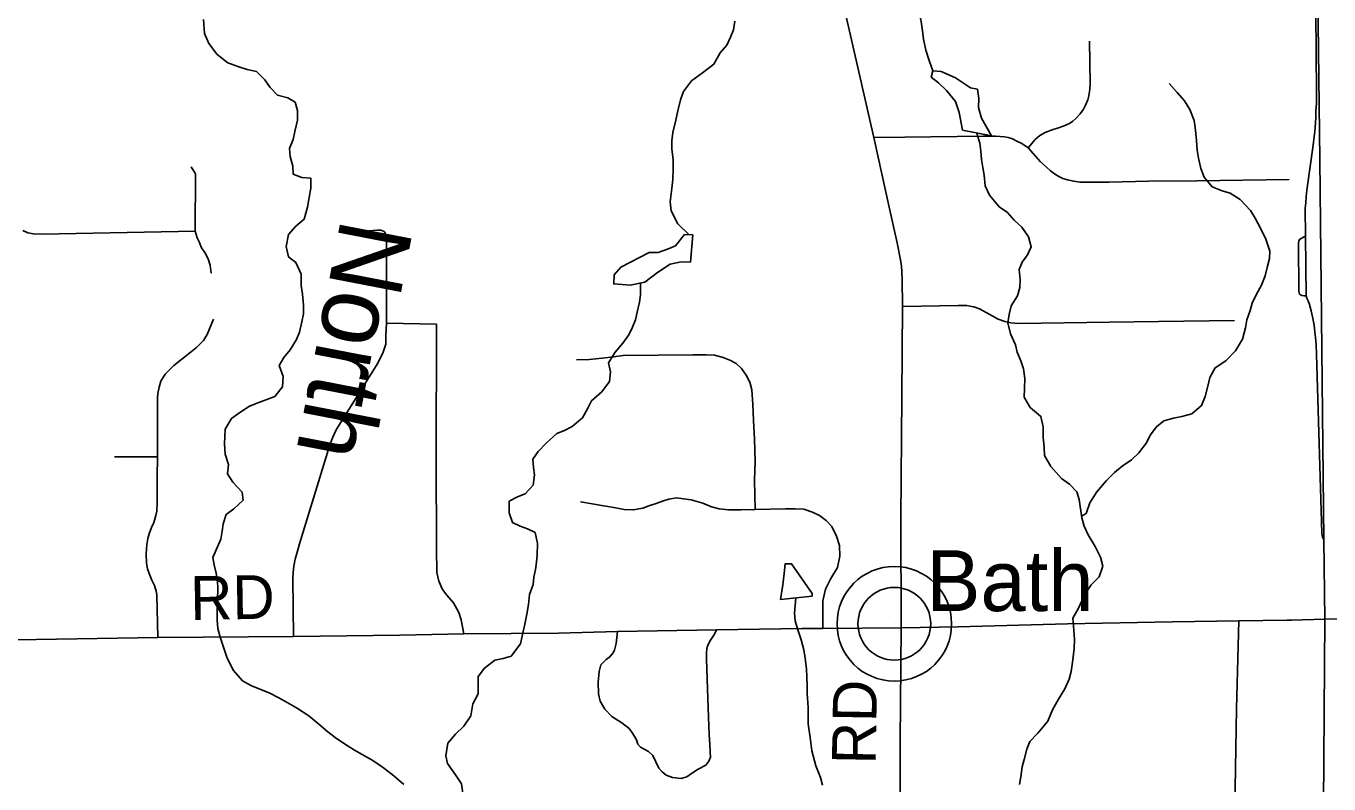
# Model space of a CAD drawing. Extents: x 0 to 34, y 0 to 22.
# Drawn here: x 4.739 to 6.431, y 14.753 to 15.737 of the extents above; entities that cross this region are included whole.
import ezdxf

# ---------------------------------------------------------------- set-up
doc = ezdxf.new("R2010")
doc.units = 0
for name, color, linetype in [('GM_X_County_Road', 7, 'Continuous'), ('GM_X_County_Road_Text', 7, 'Continuous'), ('GM_X_Interchange_Ramps', 7, 'Continuous'), ('GM_X_Interstate_Route', 7, 'Continuous'), ('GM_X_Minor_Lake', 7, 'Continuous'), ('GM_X_Minor_River', 7, 'Continuous'), ('GM_X_Minor_River_Text', 7, 'Continuous'), ('GM_X_Township_Road', 7, 'Continuous'), ('GM_X_Unincorporated', 7, 'Continuous'), ('GM_X_Unincorporated_Location', 7, 'Continuous'), ('GM_X_Unincorporated_Text', 7, 'Continuous')]:
    doc.layers.add(name, color=color, linetype=linetype)

msp = doc.modelspace()

# ---------------------------------------------------------------- linework, layer by layer
at = {"layer": 'GM_X_County_Road'}
for points in [[(5.8717, 14.1), (5.8713, 14.2404), (5.872, 14.4243), (5.8732, 14.6187), (5.8739, 14.809), (5.875, 14.9557), (5.8744, 15.0978), (5.8759, 15.2554), (5.8769, 15.3727), (5.8762, 15.4088), (5.8752, 15.4255), (5.8739, 15.4356), (5.87, 15.4555), (5.8595, 15.5018), (5.8396, 15.592), (5.8151, 15.698), (5.7885, 15.8153), (5.784, 15.8367), (5.7797, 15.8558), (5.777, 15.8765)], [(5.875, 14.9557), (5.9488, 14.9569), (6.091, 14.9609), (6.2275, 14.9636), (6.3137, 14.9647), (6.3762, 14.9657), (6.3821, 14.9658)], [(6.3821, 14.9658), (6.425, 14.9668), (6.4444, 14.9673), (6.542, 14.9681), (6.5587, 14.9685)], [(4.3412, 14.9346), (4.511, 14.937), (4.6987, 14.9398), (4.9098, 14.943), (5.086, 14.9444), (5.2239, 14.9463), (5.3069, 14.9479), (5.4298, 14.9489), (5.5067, 14.9509), (5.635, 14.953), (5.7464, 14.9549), (5.7732, 14.955), (5.875, 14.9557)]]:
    msp.add_lwpolyline(points, dxfattribs=at)
at = {"layer": 'GM_X_Interchange_Ramps'}
for points in [[(6.4131, 15.7649), (6.4139, 15.716), (6.4143, 15.6364), (6.4137, 15.6266), (6.4133, 15.6177), (6.4129, 15.6116), (6.4125, 15.605), (6.412, 15.5999), (6.4115, 15.5936), (6.41, 15.5821), (6.4019, 15.5238), (6.4008, 15.5151), (6.4003, 15.5074), (6.3998, 15.5003), (6.4001, 15.4641), (6.4009, 15.3867), (6.4018, 15.3837), (6.4036, 15.38), (6.4051, 15.3752), (6.4074, 15.3671), (6.4091, 15.3595), (6.4112, 15.3483), (6.4124, 15.3393), (6.4132, 15.3325), (6.414, 15.3232), (6.4144, 15.3109), (6.4148, 15.2962), (6.4213, 15.0791), (6.4216, 15.0755), (6.4224, 15.0727), (6.4239, 15.0701)], [(6.4001, 15.4641), (6.3976, 15.4629), (6.3953, 15.4615), (6.3928, 15.46), (6.3913, 15.4579), (6.3909, 15.4552), (6.3913, 15.392), (6.3924, 15.3889), (6.3953, 15.3872), (6.3983, 15.3866), (6.4009, 15.3867)]]:
    msp.add_lwpolyline(points, dxfattribs=at)
at = {"layer": 'GM_X_Interstate_Route'}
msp.add_lwpolyline([(6.419, 14.1), (6.4211, 14.4229), (6.425, 14.9668), (6.4239, 15.0701), (6.4187, 15.5636), (6.4161, 15.7761), (6.4147, 15.8905), (6.4116, 16.1673), (6.4105, 16.2537), (6.4089, 16.369), (6.4076, 16.42), (6.4063, 16.4687), (6.4018, 16.5458), (6.3968, 16.6242), (6.3897, 16.7077), (6.3766, 16.863), (6.3715, 16.9335)], dxfattribs=at)
at = {"layer": 'GM_X_Minor_Lake'}
for points in [[(5.9925, 15.5942), (5.9794, 15.6173), (5.9754, 15.6309), (5.9757, 15.6427), (5.9741, 15.6548), (5.965, 15.6566), (5.9455, 15.6694), (5.9268, 15.6779), (5.9162, 15.6786), (5.914, 15.6706), (5.9236, 15.6631), (5.9339, 15.6533), (5.9454, 15.639), (5.9505, 15.6246), (5.9545, 15.6018)], [(5.9545, 15.6018), (5.9925, 15.5942)], [(5.6043, 15.4656), (5.5937, 15.4663), (5.5817, 15.4513), (5.5714, 15.4471), (5.5593, 15.4428), (5.5476, 15.4427), (5.5109, 15.4237), (5.5023, 15.4137), (5.5017, 15.402), (5.5229, 15.4003), (5.5419, 15.4042), (5.5584, 15.4169), (5.575, 15.4277), (5.5894, 15.4305), (5.6016, 15.4302)], [(5.6016, 15.4302), (5.6043, 15.4656)], [(5.7596, 14.9968), (5.7592, 15.0002), (5.7326, 15.0387), (5.7243, 15.0386), (5.7229, 15.026), (5.7215, 15.0116), (5.7182, 14.9926)], [(5.7182, 14.9926), (5.7596, 14.9968)]]:
    msp.add_lwpolyline(points, dxfattribs=at)
at = {"layer": 'GM_X_Minor_River'}
for points in [[(5.9162, 15.6786), (5.9115, 15.6919), (5.9072, 15.7055), (5.9041, 15.7195), (5.9025, 15.7305), (5.9008, 15.7427), (5.898, 15.7567), (5.8915, 15.7769)], [(5.1889, 14.7836), (5.1748, 14.7911), (5.1649, 14.7967), (5.1519, 14.8049), (5.14, 14.8132), (5.1305, 14.8207), (5.1186, 14.8308), (5.1056, 14.8413), (5.0896, 14.8518), (5.0774, 14.8589), (5.0667, 14.8649), (5.0553, 14.8709), (5.0412, 14.8764), (5.0313, 14.8805), (5.0195, 14.8869), (5.0079, 14.9001), (4.9998, 14.9163), (4.9905, 14.9436), (4.9877, 14.955), (4.9869, 14.9656), (4.9867, 14.9789), (4.987, 14.9922), (4.9876, 15.0066), (4.9872, 15.0161), (4.9852, 15.0267), (4.9828, 15.0373), (4.9812, 15.0468), (4.9916, 15.0709), (4.993, 15.0811), (4.9945, 15.0906), (4.9985, 15.1028), (5.0083, 15.1101), (5.0204, 15.1213), (5.0191, 15.1319), (5.0072, 15.1447), (4.9999, 15.1556), (5.0013, 15.1678), (4.9971, 15.1811), (4.9962, 15.1944), (4.9965, 15.2039), (4.9971, 15.2137), (5.0054, 15.2275), (5.0163, 15.2352), (5.0287, 15.2433), (5.0408, 15.2483), (5.0514, 15.2522), (5.0616, 15.2561), (5.0714, 15.2684), (5.0724, 15.2817), (5.0674, 15.2961), (5.0733, 15.3064), (5.0816, 15.3163), (5.0898, 15.3301), (5.0935, 15.3396), (5.0968, 15.353), (5.0986, 15.3632), (5.0989, 15.3746), (5.0976, 15.3887), (5.0956, 15.4001), (5.0959, 15.4145), (5.0889, 15.43), (5.0794, 15.4371), (5.0762, 15.4508), (5.0795, 15.4664), (5.0889, 15.4771), (5.0998, 15.4863), (5.1042, 15.5016), (5.106, 15.5141), (5.1085, 15.5263), (5.1084, 15.5392), (5.0966, 15.5402), (5.0856, 15.5447), (5.0851, 15.555), (5.0816, 15.5675), (5.0807, 15.5777), (5.0856, 15.5895), (5.0874, 15.5998), (5.091, 15.6147), (5.0909, 15.6272), (5.0882, 15.6378), (5.0783, 15.6434), (5.0649, 15.6471), (5.0557, 15.6569), (5.0484, 15.6671), (5.0377, 15.6776), (5.0256, 15.6805), (5.0149, 15.6838), (5.0004, 15.689), (4.9867, 15.6999), (4.9759, 15.7139), (4.9701, 15.7271), (4.9688, 15.7453)], [(5.5995, 15.4659), (5.5848, 15.4799), (5.5763, 15.4969), (5.5751, 15.5086), (5.5772, 15.5258), (5.5786, 15.5375), (5.5789, 15.5516), (5.5787, 15.563), (5.5771, 15.5774), (5.577, 15.5877), (5.5784, 15.5987), (5.5825, 15.6147), (5.5854, 15.6288), (5.5887, 15.6421), (5.5924, 15.6516), (5.6029, 15.6658), (5.6168, 15.6762), (5.6315, 15.6873), (5.6401, 15.7019), (5.6484, 15.7118), (5.6532, 15.7225), (5.6573, 15.732), (5.6591, 15.7431)], [(6.1093, 15.1007), (6.1153, 15.1042), (6.1201, 15.1179), (6.1291, 15.1324), (6.1415, 15.147), (6.152, 15.1573), (6.1618, 15.1654), (6.1739, 15.1739), (6.1837, 15.1827), (6.1938, 15.1957), (6.1983, 15.2056), (6.2065, 15.2167), (6.2163, 15.2244), (6.2288, 15.2279), (6.2394, 15.2299), (6.2523, 15.2335), (6.2651, 15.2442), (6.2699, 15.2561), (6.2732, 15.2694), (6.2757, 15.2804), (6.2828, 15.293), (6.2968, 15.3023), (6.3092, 15.3153), (6.3182, 15.3302), (6.3222, 15.3451), (6.324, 15.3553), (6.3281, 15.3675), (6.331, 15.377), (6.3359, 15.3877), (6.343, 15.4003), (6.3478, 15.4125), (6.3504, 15.4232), (6.3533, 15.435), (6.3536, 15.4445), (6.3485, 15.46), (6.3415, 15.4744), (6.3346, 15.4873), (6.3288, 15.4975), (6.3154, 15.5118), (6.3024, 15.52), (6.2918, 15.5229), (6.2788, 15.5281), (6.2685, 15.5406), (6.2642, 15.5519), (6.261, 15.5652), (6.2594, 15.5758), (6.2585, 15.588), (6.2573, 15.6016), (6.2557, 15.6142), (6.2498, 15.6285), (6.2429, 15.6395), (6.2333, 15.6504), (6.223, 15.6621)], [(6.0234, 15.3229), (6.0168, 15.3373), (6.0133, 15.3517), (6.0151, 15.3623), (6.018, 15.3734), (6.0262, 15.3867), (6.0292, 15.3974), (6.0295, 15.4077), (6.0282, 15.4206), (6.0323, 15.4301), (6.039, 15.44), (6.0439, 15.4503), (6.0403, 15.4632), (6.0315, 15.4757), (6.0219, 15.4847), (6.0127, 15.4953), (6.0028, 15.5016), (5.9898, 15.5171), (5.984, 15.5292), (5.9827, 15.5432), (5.9811, 15.5531), (5.9791, 15.5637), (5.9786, 15.5743), (5.977, 15.5846), (5.9731, 15.5975)], [(5.3058, 14.741), (5.3038, 14.7532), (5.2961, 14.7649), (5.2857, 14.7796), (5.2837, 14.7894), (5.2862, 14.8058), (5.296, 14.8177), (5.3072, 14.828), (5.3162, 14.8414), (5.3188, 14.857), (5.3258, 14.87), (5.3257, 14.8806), (5.3256, 14.8924), (5.3339, 14.9035), (5.3471, 14.9139), (5.3581, 14.9159), (5.3683, 14.919), (5.3807, 14.9347), (5.3843, 14.9507), (5.3861, 14.9606), (5.389, 14.9732), (5.3912, 14.9861), (5.3922, 14.999), (5.397, 15.012), (5.3981, 15.0215), (5.3999, 15.0314), (5.4013, 15.0409), (5.4024, 15.0504), (5.4026, 15.0652), (5.3995, 15.0792), (5.3895, 15.0841), (5.38, 15.0878), (5.3701, 15.0926), (5.3658, 15.1048), (5.3661, 15.12), (5.3766, 15.1257), (5.3865, 15.1296), (5.397, 15.1408), (5.3988, 15.1544), (5.3976, 15.1639), (5.3967, 15.1746), (5.4034, 15.1845), (5.4143, 15.1956), (5.4279, 15.2079), (5.4377, 15.2118), (5.4479, 15.2172), (5.4611, 15.2283), (5.4682, 15.2406), (5.473, 15.2501), (5.4862, 15.262), (5.496, 15.2754), (5.4974, 15.2879), (5.495, 15.2997), (5.5036, 15.3135), (5.5134, 15.3253), (5.5212, 15.336), (5.5261, 15.346), (5.5298, 15.3555), (5.532, 15.3654), (5.5353, 15.3783), (5.5363, 15.3878), (5.5365, 15.4031)], [(6.0286, 14.7524), (6.0304, 14.7623), (6.0322, 14.7752), (6.0347, 14.7847), (6.038, 14.798), (6.0421, 14.8083), (6.0526, 14.8191), (6.0654, 14.8344), (6.0713, 14.8493), (6.0792, 14.863), (6.0874, 14.8764), (6.093, 14.889), (6.0959, 14.8992), (6.0981, 14.9141), (6.0998, 14.9289), (6.1001, 14.9399), (6.0992, 14.9528), (6.0979, 14.9684), (6.1047, 14.9802), (6.1099, 14.9917), (6.1147, 15.0012), (6.1218, 15.0115), (6.132, 15.0219), (6.1368, 15.0356), (6.134, 15.0474), (6.1271, 15.0614), (6.1178, 15.0765), (6.1128, 15.0878), (6.1097, 15.0984), (6.106, 15.1223), (6.1029, 15.1322), (6.0937, 15.1423), (6.0834, 15.1495), (6.0692, 15.1649), (6.0611, 15.1793), (6.0606, 15.1899), (6.0594, 15.2032), (6.0596, 15.2165), (6.0565, 15.2301), (6.0427, 15.2418), (6.0346, 15.255), (6.0353, 15.2664), (6.0355, 15.2793), (6.0339, 15.2918), (6.0304, 15.3021), (6.0258, 15.3134), (6.0234, 15.3229)], [(5.7728, 14.7515), (5.7704, 14.7613), (5.7642, 14.7765), (5.7591, 14.7962), (5.7567, 14.8133), (5.7542, 14.8311), (5.7541, 14.8524), (5.7531, 14.8706), (5.753, 14.8801), (5.7525, 14.8926), (5.7521, 14.9021), (5.7501, 14.9165), (5.7484, 14.9271), (5.7449, 14.94), (5.7406, 14.9529), (5.7375, 14.9646), (5.7366, 14.9749), (5.7383, 14.9946)], [(5.229, 14.7525), (5.216, 14.7634), (5.2026, 14.7739), (5.1889, 14.7836)]]:
    msp.add_lwpolyline(points, dxfattribs=at)
at = {"layer": 'GM_X_Township_Road'}
msp.add_line((4.8533, 15.1775), (4.9092, 15.1775), dxfattribs=at)
for points in [[(6.0398, 15.5787), (6.049, 15.5893), (6.0551, 15.5946), (6.062, 15.5986), (6.0711, 15.602), (6.0791, 15.6045), (6.0868, 15.6072), (6.0936, 15.6104), (6.098, 15.6135), (6.1017, 15.6168), (6.1074, 15.6226), (6.1118, 15.6288), (6.1145, 15.6342), (6.1172, 15.6411), (6.1187, 15.6462), (6.1201, 15.6548), (6.1204, 15.6622), (6.1196, 15.7172)], [(5.8396, 15.592), (5.8796, 15.5925), (5.9815, 15.5937), (5.9976, 15.5939), (6.0036, 15.5934), (6.009, 15.5929), (6.0141, 15.592), (6.0195, 15.5902), (6.0254, 15.5875), (6.0317, 15.5841), (6.0398, 15.5787), (6.0561, 15.5605), (6.0635, 15.5539), (6.0689, 15.5488), (6.074, 15.5451), (6.0799, 15.5416), (6.0851, 15.539), (6.0909, 15.5372), (6.0991, 15.5352), (6.1072, 15.5342), (6.145, 15.5343), (6.1962, 15.5355), (6.2588, 15.536), (6.3787, 15.5374)], [(4.9788, 15.4161), (4.9775, 15.4266), (4.975, 15.4347), (4.9706, 15.443), (4.9664, 15.449), (4.9635, 15.4565), (4.9607, 15.4619), (4.9582, 15.4706), (4.9584, 15.5448), (4.9531, 15.554)], [(4.7342, 15.4713), (4.7409, 15.4685), (4.748, 15.4669), (4.7593, 15.4667), (4.9582, 15.4706)], [(5.086, 14.9444), (5.0851, 15.0195), (5.0853, 15.0274), (5.0863, 15.0356), (5.0878, 15.0447), (5.0903, 15.0522), (5.0938, 15.0648), (5.1331, 15.1931), (5.1371, 15.2032), (5.139, 15.2078), (5.1411, 15.2127), (5.1945, 15.2978), (5.2019, 15.3121), (5.2056, 15.3239), (5.2058, 15.3345), (5.2065, 15.3511), (5.2065, 15.4621), (5.2053, 15.4669), (5.2035, 15.4702), (5.1993, 15.4718), (5.1943, 15.472), (5.166, 15.4695)], [(5.8769, 15.3727), (5.9491, 15.374), (5.9601, 15.374), (5.9642, 15.3733), (5.9692, 15.3725), (5.9765, 15.3698), (5.9891, 15.3627), (6.0011, 15.3561), (6.0094, 15.3531), (6.0176, 15.3515), (6.0274, 15.3506), (6.1454, 15.3524), (6.2093, 15.3531), (6.308, 15.3546)], [(4.9098, 14.943), (4.9082, 14.9984), (4.9076, 15.0034), (4.9052, 15.0108), (4.9019, 15.0175), (4.8983, 15.0262), (4.8964, 15.0324), (4.8951, 15.0396), (4.8946, 15.0516), (4.8953, 15.0638), (4.8966, 15.0718), (4.8983, 15.0778), (4.9015, 15.0857), (4.9045, 15.0923), (4.9071, 15.1015), (4.9082, 15.1069), (4.9086, 15.1175), (4.9086, 15.1513), (4.9092, 15.1775), (4.9092, 15.254), (4.9097, 15.26), (4.9112, 15.2681), (4.9137, 15.2757), (4.9192, 15.2847), (4.9303, 15.2963), (4.9514, 15.3124), (4.96, 15.3194), (4.969, 15.3285), (4.9736, 15.3365), (4.9821, 15.3562)], [(5.3069, 14.9479), (5.3036, 14.9659), (5.3006, 14.9756), (5.2936, 14.9883), (5.2849, 14.9979), (5.2792, 15.0056), (5.2746, 15.0162), (5.2719, 15.0276), (5.2716, 15.0579), (5.271, 15.174), (5.2715, 15.3497), (5.2065, 15.3511)], [(5.4533, 15.3034), (5.4702, 15.3039), (5.4867, 15.3058), (5.5013, 15.3072), (5.514, 15.3091), (5.6043, 15.31), (5.6217, 15.31), (5.6325, 15.3095), (5.6438, 15.3067), (5.6523, 15.303), (5.6607, 15.2987), (5.6678, 15.2921), (5.6739, 15.2837), (5.6786, 15.2747), (5.681, 15.2644), (5.6824, 15.2456), (5.6833, 15.2249), (5.6843, 15.2004), (5.6852, 15.1722), (5.6843, 15.1473), (5.6855, 15.1092)], [(5.4585, 15.119), (5.4735, 15.1167), (5.4862, 15.1143), (5.5017, 15.112), (5.5154, 15.1091), (5.5271, 15.1087), (5.5394, 15.111), (5.5474, 15.1139), (5.5568, 15.1171), (5.5652, 15.12), (5.5732, 15.1228), (5.5831, 15.1242), (5.5925, 15.1233), (5.6024, 15.1218), (5.6175, 15.1176), (5.6287, 15.1129), (5.6386, 15.1101), (5.6509, 15.1087), (5.6673, 15.1087), (5.6855, 15.1092), (5.7247, 15.1101), (5.7374, 15.1101), (5.7487, 15.1096), (5.76, 15.1059), (5.7689, 15.1016), (5.7774, 15.095), (5.7849, 15.087), (5.791, 15.0748), (5.7948, 15.0626), (5.7953, 15.0489), (5.7925, 15.0339), (5.7835, 15.0198), (5.7765, 15.0057), (5.7732, 14.9906), (5.7732, 14.955)], [(6.3084, 14.7218), (6.3105, 14.8505), (6.3137, 14.9647)], [(5.5067, 14.9509), (5.5048, 14.9355), (5.5025, 14.9267), (5.5007, 14.9226), (5.4968, 14.9182), (5.4917, 14.9147), (5.485, 14.9078), (5.4827, 14.8991), (5.4816, 14.8852), (5.4818, 14.8698), (5.4841, 14.8606), (5.4903, 14.85), (5.4991, 14.8408), (5.5122, 14.8325), (5.5216, 14.8251), (5.526, 14.8189), (5.5311, 14.8101), (5.5329, 14.8048), (5.5364, 14.8007), (5.5419, 14.7977), (5.547, 14.7952), (5.5525, 14.7901), (5.5562, 14.7816), (5.5601, 14.7737), (5.5645, 14.7687), (5.5696, 14.7643), (5.5779, 14.7615), (5.5891, 14.7601), (5.5965, 14.7622), (5.6027, 14.7664), (5.6113, 14.7724), (5.6212, 14.7774), (5.6253, 14.7825), (5.6272, 14.7878), (5.6269, 14.7945), (5.6265, 14.8041), (5.6258, 14.8171)], [(5.6258, 14.8171), (5.6248, 14.8396), (5.6237, 14.8645), (5.6221, 14.9152), (5.6221, 14.9228), (5.6225, 14.929), (5.6237, 14.9332), (5.6274, 14.9398), (5.6324, 14.9474), (5.635, 14.953)]]:
    msp.add_lwpolyline(points, dxfattribs=at)
at = {"layer": 'GM_X_Unincorporated'}
for radius in [0.0744, 0.0472]:
    msp.add_circle((5.8661, 14.9609), radius, dxfattribs=at)
at = {"layer": 'GM_X_Unincorporated_Location'}
msp.add_line((5.8661, 14.9609), (5.8661, 14.9609), dxfattribs=at)

# ---------------------------------------------------------------- texts
at = {"layer": 'GM_X_County_Road_Text'}
for rotation, p in [(0.9872, (4.9521, 14.9658)), (89.0134, (5.8418, 14.7781))]:
    msp.add_text('RD', height=0.05682, rotation=rotation, dxfattribs=at).set_placement(p)
at = {"layer": 'GM_X_Minor_River_Text'}
msp.add_text('North', height=0.09473, rotation=259.0829, dxfattribs=at).set_placement((5.1479, 15.4891))
at = {"layer": 'GM_X_Unincorporated_Text'}
msp.add_text('Bath', height=0.07898, rotation=0, dxfattribs=at).set_placement((5.9075, 14.9774))

doc.saveas('drawing.dxf')
